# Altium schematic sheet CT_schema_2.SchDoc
size 300 x 163 mm
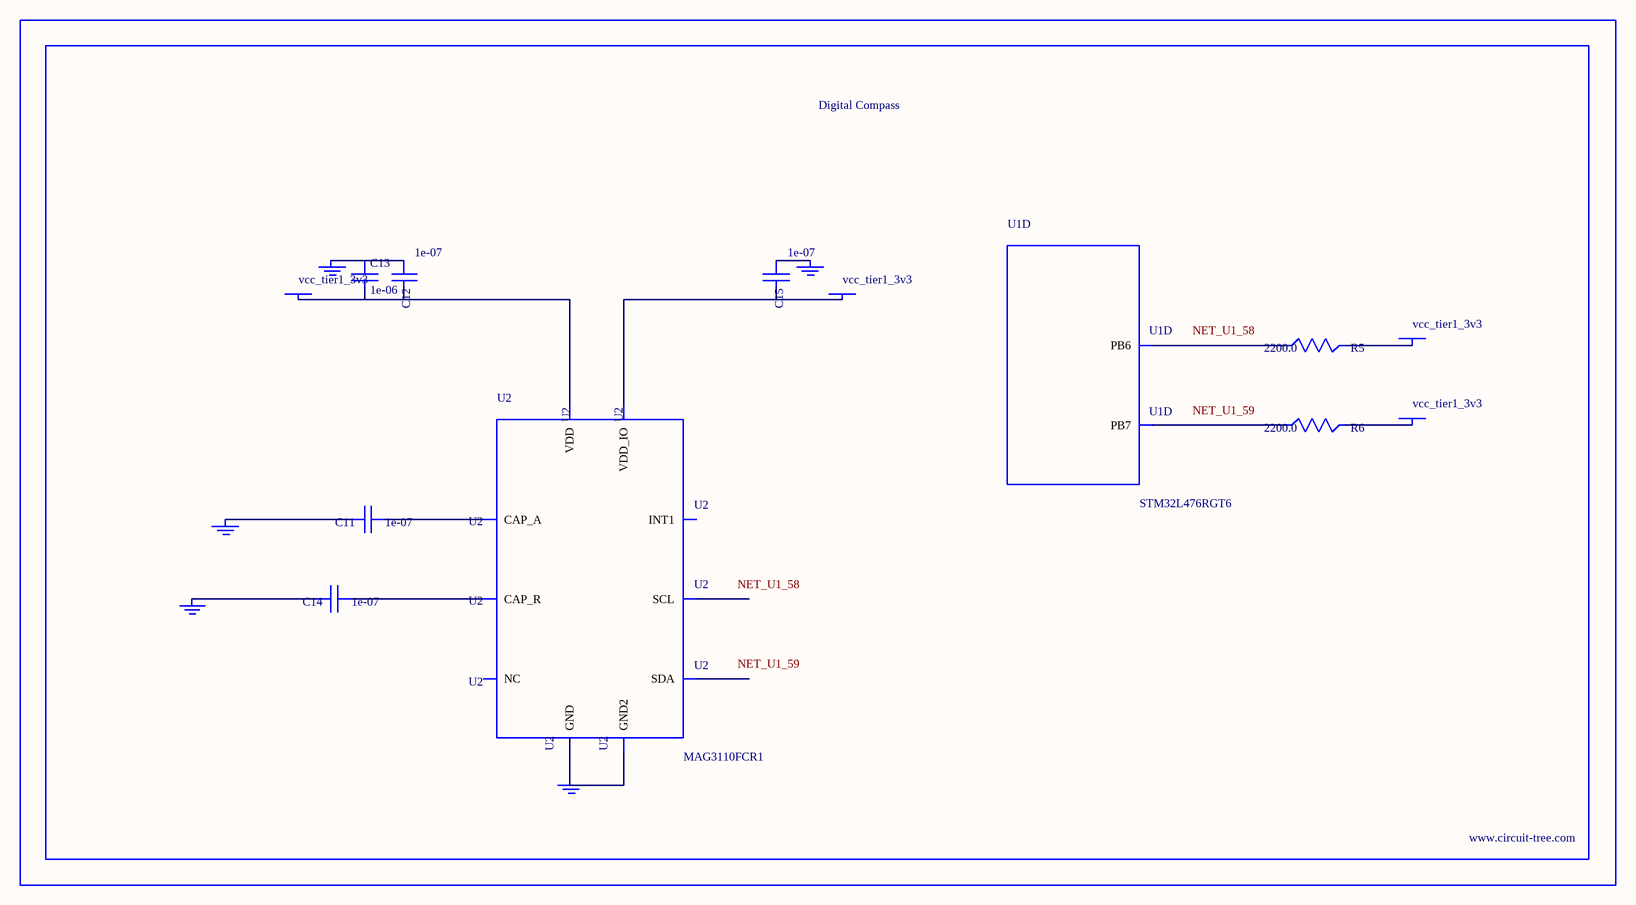
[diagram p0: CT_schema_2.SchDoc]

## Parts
BORDER1  (no value)
C11  1e-07  [C0402]
C12  1e-07  [C0402]
C13  1e-06  [C0603]
C14  1e-07  [C0402]
C15  1e-07  [C0402]
GND_INSTANCE_1_0  (no value)
GND_INSTANCE_1_1  (no value)
GND_INSTANCE_1_2  (no value)
GND_INSTANCE_1_3  (no value)
GND_INSTANCE_1_4  (no value)
POWER_INSTANCE_1_0  vcc_tier1_3v3
POWER_INSTANCE_1_1  vcc_tier1_3v3
POWER_INSTANCE_1_2  vcc_tier1_3v3
POWER_INSTANCE_1_3  vcc_tier1_3v3
R5  2200.0  [R0603]
R6  2200.0  [R0603]
U1  STM32L476RGT6  [LQFP64]  (part D of 8)
U2  MAG3110FCR1  [DFN-10]

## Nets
NetC11_1: C11.1 U2.1(CAP_A)
NetC11_2: C11.2 GND_INSTANCE_1_0.0(GND)
NetC12_1: C12.1 C13.1 GND_INSTANCE_1_1.0(GND)
NetC12_2: C12.2 C13.2 POWER_INSTANCE_1_0.0(PWR) U2.2(VDD)
NetC14_1: C14.1 U2.4(CAP_R)
NetC14_2: C14.2 GND_INSTANCE_1_2.0(GND)
NetC15_1: C15.1 GND_INSTANCE_1_3.0(GND)
NetC15_2: C15.2 POWER_INSTANCE_1_1.0(PWR) U2.8(VDD_IO)
NetGND_INSTANCE_1_4_0: GND_INSTANCE_1_4.0(GND) U2.5(GND) U2.10(GND2)
NetPOWER_INSTANCE_1_2_0: POWER_INSTANCE_1_2.0(PWR) R5.2
NetPOWER_INSTANCE_1_3_0: POWER_INSTANCE_1_3.0(PWR) R6.2
NetR5_1: R5.1 U1.58(PB6)
NetR6_1: R6.1 U1.59(PB7)

Not connected (* = marked no-connect by the designer): U2 3(NC) 6(SDA) 7(SCL) 9(INT1)

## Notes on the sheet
- Labels drawn without touching a wire or pin: NET_U1_58, NET_U1_59

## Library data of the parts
BORDER1 = BORDER_PAGE1
C11 C12 C14 C15 = C0402C104K3RACTU
C13 = C0603C105K3RACTU
GND_INSTANCE_1_0-GND_INSTANCE_1_4 = GND
POWER_INSTANCE_1_0-POWER_INSTANCE_1_3 = PWR
R5 R6 = RC0603JR-072K2L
